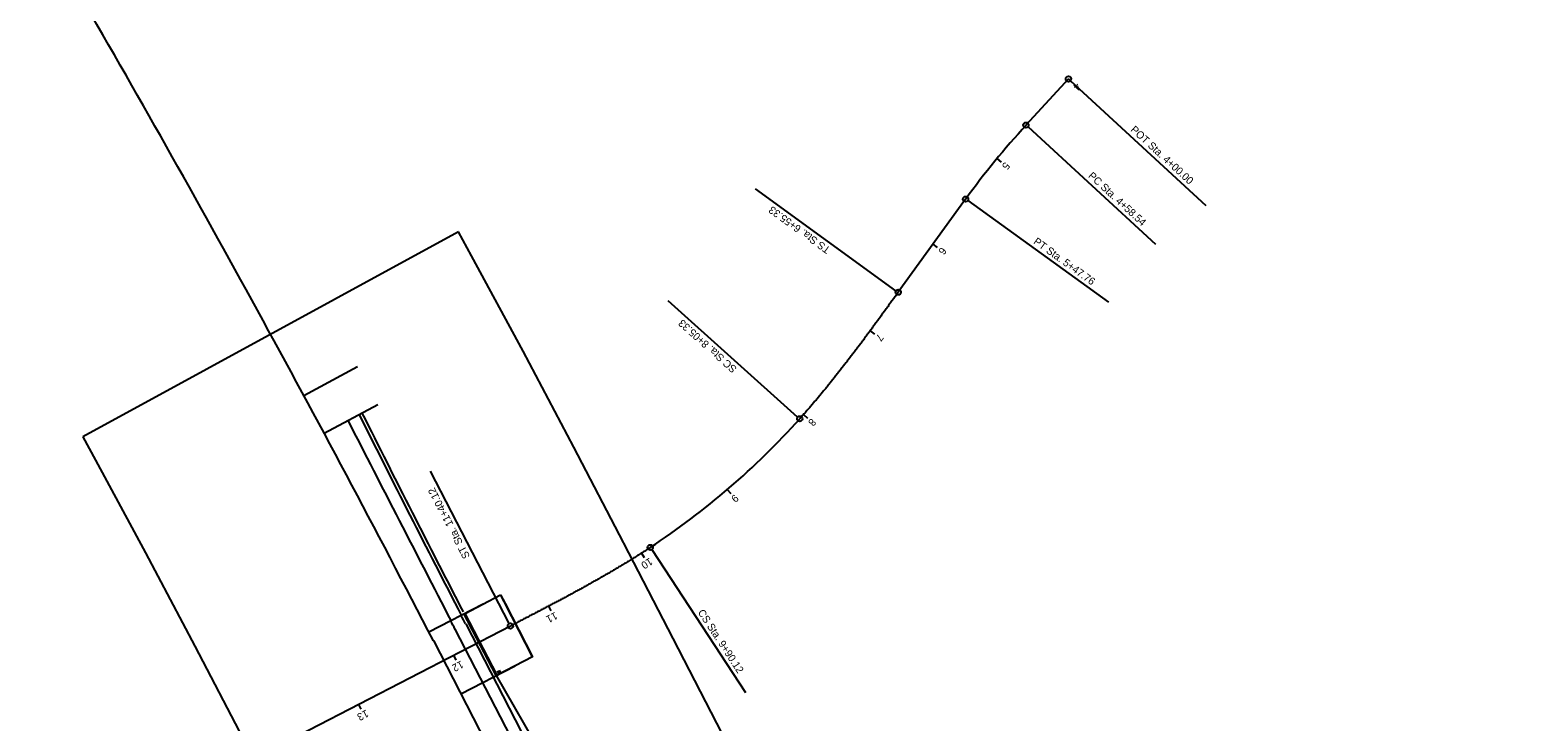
# Model space of a CAD drawing. Extents: x 21904 to 36537, y 12187 to 32963.
# Drawn here: x 23919 to 25328, y 28362 to 29009 of the extents above; entities that cross this region are included whole.
import ezdxf

# ---------------------------------------------------------------- set-up
doc = ezdxf.new("R2010")
doc.units = 0
for name, color, linetype in [('BR_P_Gen_Text', 7, 'Continuous'), ('BR_P_Rail_Object', 7, 'Continuous'), ('BR_X_Drain_Object', 7, 'Continuous'), ('GE_P_CL_50', 7, 'Continuous'), ('GE_X_CL_10', 7, 'Continuous'), ('MT_P_Drums', 7, 'Continuous'), ('SH_Border', 7, 'Continuous'), ('SH_Data', 7, 'Continuous'), ('SH_Text', 7, 'Continuous')]:
    doc.layers.add(name, color=color, linetype=linetype)

msp = doc.modelspace()

# ---------------------------------------------------------------- linework, layer by layer
at = {"layer": 'BR_P_Gen_Text'}
for p, q in [((24174.9, 28667.1), (24225.1, 28694.2)), ((24193.9, 28631.9), (24244.1, 28658.8)), ((24291.8, 28446.1), (24342.4, 28472.3)), ((24321.6, 28388.3), (24372.2, 28414.5))]:
    msp.add_line(p, q, dxfattribs=at)
at = {"layer": 'BR_P_Rail_Object'}
for p, q in [((24319.5, 28820), (23968.4, 28628.4)), ((24331.6, 28797.8), (24319.5, 28820)), ((23968.4, 28628.4), (23980.2, 28606.8))]:
    msp.add_line(p, q, dxfattribs=at)
msp.add_lwpolyline([(23980.2, 28606.8), (24026.9, 28520), (24073.1, 28432.9), (24118.2, 28346.2), (24118.7, 28345.4), (24164.6, 28256.6), (24210.5, 28167.7), (24256.4, 28078.9), (24302.3, 27990), (24657.6, 28173.6), (24611.7, 28262.5), (24565.8, 28351.3), (24519.9, 28440.1), (24474, 28529), (24473.6, 28529.8), (24427.2, 28618.9), (24379.7, 28708.5), (24331.6, 28797.8)], dxfattribs=at)
at = {"layer": 'BR_X_Drain_Object'}
for p, q in [((24357.3, 28406.8), (24355.9, 28409.7)), ((24359, 28407.7), (24357.6, 28410.5)), ((24361, 28408.7), (24355.4, 28405.8)), ((24358.2, 28407.3), (24358.2, 28407.3)), ((24358.2, 28407.3), (24358.2, 28407.3))]:
    msp.add_line(p, q, dxfattribs=at)
at = {"layer": 'GE_P_CL_50'}
msp.add_line((24295.9, 28438), (26722.8, 23740.3), dxfattribs=at)
msp.add_arc((11569.8, 21863.7), 14323.9, 27.32083, 30.12083, dxfattribs=at)
at = {"layer": 'GE_X_CL_10'}
for p, q in [((24889.5, 28963), (24849.8, 28919.9)), ((24889.5, 28963), (24893.1, 28959.6)), ((24891.3, 28961.3), (25018, 28844.8)), ((24851.7, 28918.2), (24970.9, 28808.6)), ((24822.6, 28888.6), (24826.5, 28885.4)), ((24728.3, 28765.1), (24597, 28860.2)), ((24793.4, 28850.8), (24730.4, 28763.7)), ((24795.5, 28849.3), (24926.8, 28754.3)), ((24762.8, 28808.5), (24766.9, 28805.6)), ((24636.4, 28647), (24515.4, 28755.6)), ((24704.1, 28727.6), (24708.1, 28724.6)), ((24641.8, 28649.3), (24645.6, 28646)), ((24366.7, 28454), (24293.2, 28596.3)), ((24570.6, 28579.3), (24573.8, 28575.5)), ((24500, 28523.1), (24587.7, 28389.6)), ((24490.3, 28519.8), (24493, 28515.6)), ((24403.5, 28470.2), (24405.8, 28465.8)), ((24367.9, 28451.7), (23024.4, 27757.7)), ((24314.7, 28424.3), (24317, 28419.8)), ((24225.8, 28378.4), (24228.1, 28373.9))]:
    msp.add_line(p, q, dxfattribs=at)
for centre in [(24889.5, 28963), (24849.8, 28919.9), (24793.4, 28850.8), (24730.4, 28763.7), (24638.3, 28645.4), (24498.6, 28525.2), (24367.9, 28451.7)]:
    msp.add_circle(centre, 2.5, dxfattribs=at)
for centre, radius, start, end in [((25412.3, 28402.9), 763.9, 137.4125, 144.1042), ((24105.2, 29123.6), 716.2, 303.3208, 318.1042)]:
    msp.add_arc(centre, radius, start, end, dxfattribs=at)
for points in [[(24730.4, 28763.7), (24729.2, 28762), (24728, 28760.4), (24726.8, 28758.7), (24725.6, 28757.1), (24724.4, 28755.5), (24723.2, 28753.8), (24722, 28752.2), (24720.9, 28750.5), (24719.7, 28748.9), (24718.5, 28747.3), (24717.3, 28745.6), (24716.1, 28744), (24714.9, 28742.3), (24713.7, 28740.7), (24712.5, 28739.1), (24711.3, 28737.4), (24710.1, 28735.8), (24708.9, 28734.2), (24707.7, 28732.5), (24706.5, 28730.9), (24705.3, 28729.3), (24704.1, 28727.6), (24702.9, 28726), (24701.7, 28724.4), (24700.5, 28722.7), (24699.3, 28721.1), (24698.1, 28719.5), (24696.9, 28717.9), (24695.6, 28716.2), (24694.4, 28714.6), (24693.2, 28713), (24692, 28711.4), (24690.8, 28709.8), (24689.6, 28708.1), (24688.3, 28706.5), (24687.1, 28704.9), (24685.9, 28703.3), (24684.6, 28701.7), (24683.4, 28700.1), (24682.2, 28698.5), (24680.9, 28696.9), (24679.7, 28695.3), (24678.4, 28693.7), (24677.2, 28692.1), (24675.9, 28690.5), (24674.7, 28688.9), (24673.4, 28687.3), (24672.2, 28685.7), (24670.9, 28684.1), (24669.7, 28682.5), (24668.4, 28681), (24667.1, 28679.4), (24665.8, 28677.8), (24664.6, 28676.2), (24663.3, 28674.6), (24662, 28673.1), (24660.7, 28671.5), (24659.4, 28669.9), (24658.1, 28668.4), (24656.8, 28666.8), (24655.5, 28665.3), (24654.2, 28663.7), (24652.9, 28662.2), (24651.6, 28660.6), (24650.3, 28659.1), (24649, 28657.5), (24647.7, 28656), (24646.3, 28654.5), (24645, 28653), (24643.7, 28651.4), (24642.3, 28649.9), (24641, 28648.4), (24639.6, 28646.9), (24638.3, 28645.4)], [(24498.6, 28525.2), (24496.9, 28524), (24495.2, 28522.9), (24493.5, 28521.8), (24491.8, 28520.7), (24490.1, 28519.7), (24488.4, 28518.6), (24486.7, 28517.5), (24485, 28516.4), (24483.2, 28515.3), (24481.5, 28514.3), (24479.8, 28513.2), (24478.1, 28512.1), (24476.3, 28511.1), (24474.6, 28510), (24472.9, 28509), (24471.1, 28507.9), (24469.4, 28506.9), (24467.7, 28505.8), (24465.9, 28504.8), (24464.2, 28503.8), (24462.4, 28502.7), (24460.7, 28501.7), (24458.9, 28500.7), (24457.2, 28499.7), (24455.4, 28498.7), (24453.6, 28497.7), (24451.9, 28496.7), (24450.1, 28495.6), (24448.4, 28494.6), (24446.6, 28493.6), (24444.8, 28492.7), (24443.1, 28491.7), (24441.3, 28490.7), (24439.5, 28489.7), (24437.8, 28488.7), (24436, 28487.7), (24434.2, 28486.7), (24432.4, 28485.8), (24430.7, 28484.8), (24428.9, 28483.8), (24427.1, 28482.9), (24425.3, 28481.9), (24423.5, 28480.9), (24421.7, 28480), (24420, 28479), (24418.2, 28478), (24416.4, 28477.1), (24414.6, 28476.1), (24412.8, 28475.2), (24411, 28474.2), (24409.2, 28473.3), (24407.4, 28472.3), (24405.6, 28471.4), (24403.8, 28470.4), (24402.1, 28469.5), (24400.3, 28468.6), (24398.5, 28467.6), (24396.7, 28466.7), (24394.9, 28465.7), (24393.1, 28464.8), (24391.3, 28463.9), (24389.5, 28462.9), (24387.7, 28462), (24385.9, 28461.1), (24384.1, 28460.1), (24382.3, 28459.2), (24380.5, 28458.3), (24378.7, 28457.3), (24376.9, 28456.4), (24375.1, 28455.5), (24373.3, 28454.5), (24371.5, 28453.6), (24369.7, 28452.7), (24367.9, 28451.7)]]:
    msp.add_spline(points, degree=3, dxfattribs=at)
at = {"layer": 'MT_P_Drums'}
msp.add_arc((37835.5, 35453.6), 15212.2, 206.56393, 207.34956, dxfattribs=at)
at = {"layer": 'SH_Border'}
for q in [(24328.8, 28455), (24459.7, 28223.3)]:
    msp.add_line((24354.5, 28405.3), q, dxfattribs=at)
msp.add_arc((11569.8, 21863.7), 14360.9, 27.32083, 27.35709, dxfattribs=at)
at = {"layer": 'SH_Data'}
for p, q in [((24326.1, 28453.6), (24801.6, 27533.3)), ((24791.8, 27528.2), (24316.4, 28448.6))]:
    msp.add_line(p, q, dxfattribs=at)
for centre, radius, start, end in [((37835.5, 35453.6), 15215.2, 206.56425, 207.35709), ((67222.1, 50658.3), 48313.2, 207.10762, 207.35709), ((11569.8, 21863.7), 14346.9, 27.32083, 27.35709), ((11569.8, 21863.7), 14357.9, 27.32083, 27.35709)]:
    msp.add_arc(centre, radius, start, end, dxfattribs=at)
at = {"layer": 'SH_Text'}
msp.add_line((24388.7, 28423), (24363, 28472.7), dxfattribs=at)
msp.add_lwpolyline([(24358.8, 28480.8), (24363, 28472.7), (24388.7, 28423), (24355.4, 28405.8), (24329.7, 28455.5), (24325.5, 28463.5)], close=True, dxfattribs=at)
msp.add_arc((11611.6, 21885.3), 14352.4, 27.32083, 27.35707, dxfattribs=at)

# ---------------------------------------------------------------- texts
at = {"layer": 'GE_X_CL_10'}
for s, rotation, p in [('4', 227.4125, (24896.7, 28959.8)), ('POT Sta. 4+00.00', 317.4125, (24947, 28914.8)), ('5', 230.5221, (24830.1, 28885.9)), ('PC Sta. 4+58.54', 317.4125, (24907.4, 28871.7)), ('TS Sta. 6+55.33', 144.1042, (24667.6, 28804.8)), ('6', 234.1042, (24770.5, 28806.3)), ('PT Sta. 5+47.76', 324.1042, (24856.2, 28809.7)), ('SC Sta. 8+05.33', 138.1042, (24580.1, 28692.8)), ('7', 233.5721, (24711.8, 28725.4)), ('8', 228.5232, (24649.1, 28646.3)), ('ST Sta. 11+40.12', 117.3208, (24330.3, 28516.8)), ('9', 220.5307, (24577.5, 28575.3)), ('10', 212.5567, (24498.1, 28515.9)), ('CS Sta. 9+90.12', 303.3208, (24542.7, 28464.4)), ('11', 207.7501, (24409.7, 28465.1)), ('12', 207.3208, (24321.9, 28419.6)), ('13', 207.3208, (24233.1, 28373.7))]:
    msp.add_text(s, height=7, rotation=rotation, dxfattribs=at).set_placement(p)

doc.saveas('drawing.dxf')
